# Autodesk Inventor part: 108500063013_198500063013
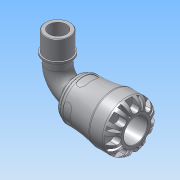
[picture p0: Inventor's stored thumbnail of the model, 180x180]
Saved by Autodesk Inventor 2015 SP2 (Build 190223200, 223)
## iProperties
Created: 2016-12
Part Number: 108500063013_198500063013
Material: PVC-Piping
Description: PLASSON 90° ELBOW WITH THREADED MALE OFFTAKE 63-1.1/4" SERIES 1
Document SubType Name: Modeling
Designer: KIM
Mass: 664.223 g
Surface Area: 733.008 cm^2
Volume: 474.445 cm^3
Density: 1.4 g/cm^3
Appearance: Smooth - White
Author: KIM
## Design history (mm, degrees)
derived "1085.ipt"
feature "Solid1::1085.ipt"
tag "TaggingFeature1"
body "Solid1"
other parameters: "d1" = 37.8, "d2" = 63, "d3" = 78.75, "d4" = 103, "d8" = 87.55, "d13" = 9.7, "d14" = 9.7, "d15" = 0, "d17" = 360 deg, "d19" = 8 deg, "d20" = 1.26, "d21" = 1.26, "d22" = 8 deg, "d24" = 0, "d26" = 360 deg, "d33" = 10.3, "d43" = 80.34, "d51" = 1.03, "d54" = 22.05, "d55" = 13.86, "d57" = 19.012, "d58" = 0, "d74" = 0, "d82" = 1.26, "d115" = 360 deg, "d207" = 90 deg, "d228" = 18.7425, "d247" = 2.06, "d248" = 5.4, "d268" = 48.1525, "d269" = 5.4, "d270" = 143, "d276" = 41.91, "d277" = 22, "d278" = 46.101, "d279" = 76, "d280" = 24.2, "d281" = 6.2865, "d283" = 37.719, "d286" = 0, "d287" = 0, "d288" = 29.337, "d290" = 21.3105, "d292" = 30 deg, "d_" = 63, "E_" = 103, "A_" = 143, "A_1" = 76, "l_2" = 22, "R_" = 41.91, "d9" = 12.125, "d11" = 103, "d12" = 78.75, "d289" = 29.337
